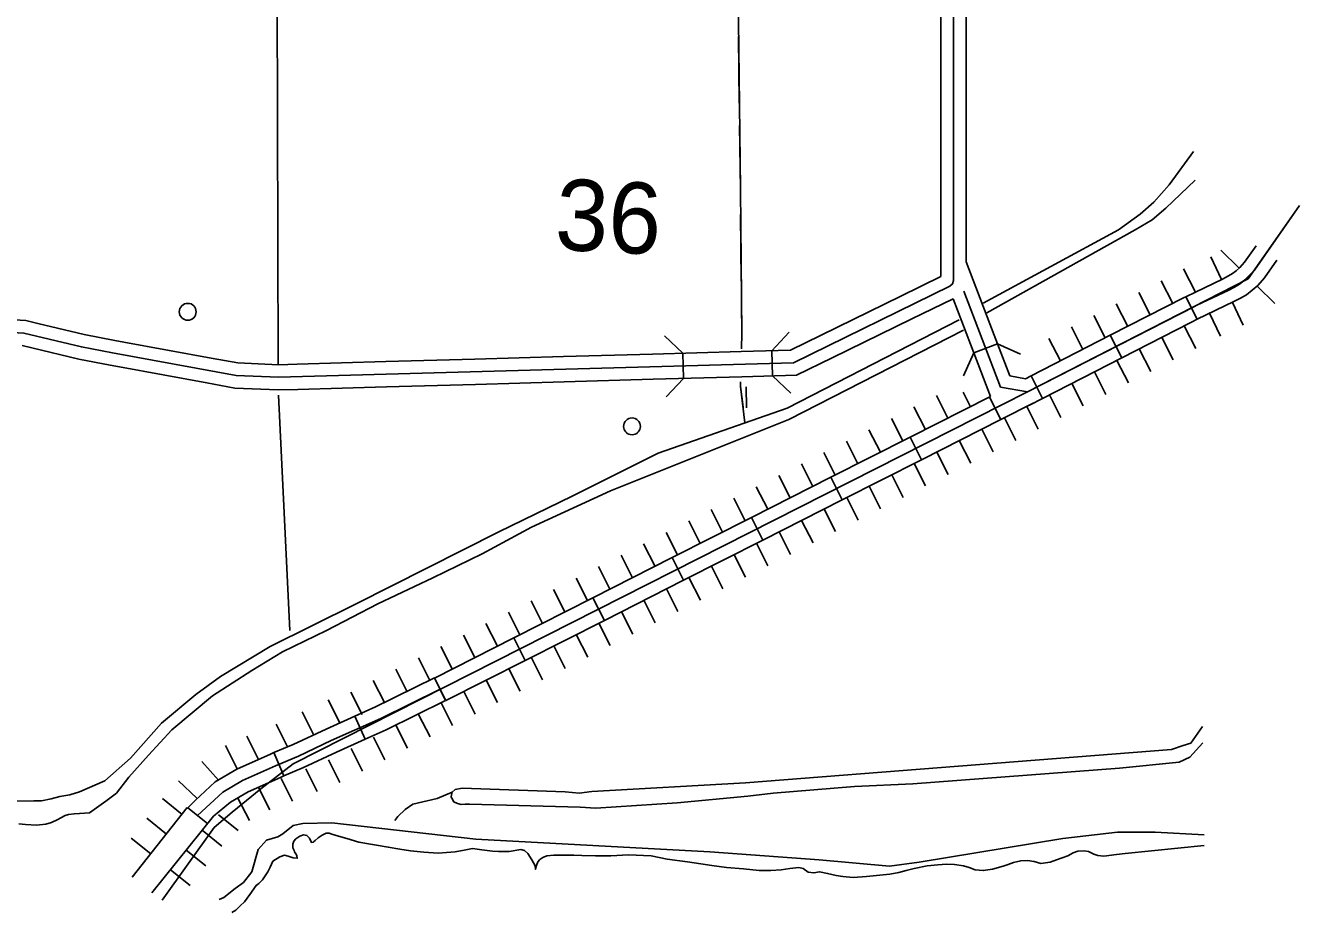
# Model space of a CAD drawing. Extents: x -4306 to 3843, y 131 to 8341.
# Drawn here: x 1170 to 2381, y 131 to 974 of the extents above; entities that cross this region are included whole.
import ezdxf

# ---------------------------------------------------------------- set-up
doc = ezdxf.new("R2010")
doc.units = 0
for name, color, linetype in [('32', 7, 'Continuous'), ('38', 7, 'Continuous'), ('52', 7, 'Continuous'), ('55', 7, 'Continuous'), ('56', 7, 'Continuous'), ('57', 7, 'Continuous'), ('63', 7, 'Continuous')]:
    doc.layers.add(name, color=color, linetype=linetype)

msp = doc.modelspace()

# ---------------------------------------------------------------- linework, layer by layer
at = {"layer": '32'}
for p, q in [((2040.2, 1016.8), (2040.1, 932.4)), ((2064.2, 1016.8), (2064.1, 932.4)), ((2040.1, 932.4), (2040.1, 847.9)), ((2064.1, 932.4), (2064.1, 847.9)), ((2040.1, 847.9), (2040.1, 763.4)), ((2064.1, 847.9), (2064.1, 763.4)), ((2338.4, 741.4), (2381.1, 802.6)), ((2040.1, 763.4), (2040.1, 735.2)), ((2064.1, 763.4), (2064.1, 748.9)), ((2328.9, 748.8), (2339.8, 764.4)), ((2090.7, 679.7), (2064.1, 749.2)), ((2317.4, 738), (2321, 740.8)), ((2321, 740.8), (2324.5, 743.8)), ((2324.5, 743.8), (2328.9, 748.8)), ((2333, 735.3), (2338.4, 741.4)), ((2347.8, 734), (2359.5, 750.7)), ((2040.1, 735.2), (2002.2, 716.7)), ((2282.1, 720.5), (2307.9, 732.8)), ((2307.9, 732.8), (2313.5, 735.9)), ((2313.5, 735.9), (2317.4, 738)), ((2319.3, 725.3), (2324, 728)), ((2324, 728), (2328.6, 731.5)), ((2328.6, 731.5), (2333, 735.3)), ((2341.5, 726.7), (2347.8, 734)), ((2002.2, 716.7), (1926.3, 679.6)), ((2096.8, 630.3), (2061.9, 721.4)), ((2271.5, 715.3), (2201.2, 679.4)), ((2273, 716), (2271.5, 715.3)), ((2282.1, 720.5), (2273, 716)), ((2273, 716), (2283.8, 694.8)), ((2283.6, 708), (2313.4, 722.1)), ((2313.4, 722.1), (2319.3, 725.3)), ((2318.8, 711.4), (2325.1, 714.8)), ((2325.1, 714.8), (2330.6, 717.9)), ((2330.6, 717.9), (2336.2, 722.2)), ((2336.2, 722.2), (2341.5, 726.7)), ((2051.8, 714.2), (2012.7, 695.1)), ((2068.3, 671.1), (2051.8, 714.2)), ((2281.9, 707.1), (2122.4, 625.6)), ((2283.8, 694.8), (2318.8, 711.4)), ((1170.2, 693.5), (1136.7, 695.4)), ((1181.5, 690.7), (1170.2, 693.5)), ((1225.5, 680.1), (1181.5, 690.7)), ((2012.7, 695.1), (1936.8, 658)), ((2277.3, 691.3), (2212.1, 658)), ((2279.1, 692.3), (2277.3, 691.3)), ((2283.8, 694.8), (2279.1, 692.3)), ((1254.9, 674.6), (1225.5, 680.1)), ((1926.3, 679.6), (1897.1, 665.3)), ((2093.9, 671.4), (2090.7, 679.7)), ((2201.2, 679.4), (2126, 640.9)), ((2201.2, 679.4), (2212.1, 658)), ((1175.9, 667.4), (1166.7, 669.6)), ((1220.5, 656.7), (1175.9, 667.4)), ((1263.4, 673), (1254.9, 674.6)), ((1346.5, 657.8), (1263.4, 673)), ((2071.5, 662.8), (2068.3, 671.1)), ((2093.9, 671.4), (2071.5, 662.8)), ((2105.6, 640.9), (2093.9, 671.4)), ((1250.5, 651), (1220.5, 656.7)), ((1371.7, 653.2), (1346.5, 657.8)), ((1512.5, 654.4), (1428.1, 652)), ((1597, 656.8), (1512.5, 654.4)), ((1681.4, 659.2), (1597, 656.8)), ((1765.9, 661.6), (1681.4, 659.2)), ((1850.3, 664), (1765.9, 661.6)), ((1795.6, 638.4), (1794.9, 662.4)), ((1897.1, 665.3), (1850.3, 664)), ((1880, 640.8), (1879.4, 664.8)), ((1936.8, 658), (1903, 641.5)), ((2087.4, 621.3), (2071.5, 662.8)), ((2212.1, 658), (2136.9, 619.5)), ((1259.1, 649.4), (1250.5, 651)), ((1342.2, 634.2), (1259.1, 649.4)), ((1410.4, 651.5), (1371.7, 653.2)), ((1428.1, 652), (1410.4, 651.5)), ((1369, 629.3), (1342.2, 634.2)), ((1513.2, 630.4), (1428.7, 628)), ((1597.6, 632.8), (1513.2, 630.4)), ((1682.1, 635.2), (1597.6, 632.8)), ((1766.6, 637.6), (1682.1, 635.2)), ((1851, 640), (1766.6, 637.6)), ((1903, 641.5), (1851, 640)), ((2122.4, 625.6), (2096.8, 630.3)), ((2120.6, 638.1), (2105.6, 640.9)), ((2126, 640.9), (2120.6, 638.1)), ((2126, 640.9), (2136.9, 619.5)), ((1410.2, 627.5), (1369, 629.3)), ((1428.7, 628), (1410.2, 627.5)), ((1424.2, 272.3), (2122.4, 625.6)), ((2010.9, 582.6), (2087.4, 621.3)), ((2097.2, 599.4), (2086.3, 620.8)), ((2136.9, 619.5), (2124.3, 613.1)), ((2097.2, 599.4), (2127.9, 614.9)), ((2021.8, 561.2), (2097.2, 599.4)), ((1935.5, 544.5), (2010.9, 582.6)), ((2021.8, 561.2), (2010.9, 582.6)), ((1946.4, 523.1), (2021.8, 561.2)), ((1860.2, 506.3), (1935.5, 544.5)), ((1946.4, 523.1), (1935.5, 544.5)), ((1871, 484.9), (1946.4, 523.1)), ((1784.8, 468.2), (1860.2, 506.3)), ((1871, 484.9), (1860.2, 506.3)), ((1795.6, 446.8), (1871, 484.9)), ((1709.4, 430.1), (1784.8, 468.2)), ((1795.6, 446.8), (1784.8, 468.2)), ((1720.2, 408.6), (1795.6, 446.8)), ((1634, 391.9), (1709.4, 430.1)), ((1720.2, 408.6), (1709.4, 430.1)), ((1644.8, 370.5), (1720.2, 408.6)), ((1558.6, 353.8), (1634, 391.9)), ((1644.8, 370.5), (1634, 391.9)), ((1569.4, 332.4), (1644.8, 370.5)), ((1558.7, 353.9), (1502.5, 326.4)), ((1569.4, 332.4), (1558.6, 353.8)), ((1558.7, 353.9), (1569.3, 332.3)), ((1564, 343.1), (1507.6, 315.5)), ((1569.3, 332.3), (1512.7, 304.6)), ((1482.9, 317.6), (1455.6, 305.3)), ((1507.6, 315.5), (1460.6, 294.4)), ((1502.5, 326.4), (1482.9, 317.6)), ((1482.9, 317.6), (1492.7, 295.7)), ((1455.6, 305.3), (1424.4, 290.6)), ((1512.7, 304.6), (1492.7, 295.7)), ((1460.6, 294.4), (1429.3, 279.7)), ((1492.7, 295.7), (1465.6, 283.5)), ((1402.7, 281.4), (1370.8, 267.2)), ((1406.1, 282.9), (1402.7, 281.4)), ((1424.4, 290.6), (1406.1, 282.9)), ((1406.1, 282.9), (1415.5, 260.8)), ((1429.3, 279.7), (1407.5, 270.4)), ((1465.6, 283.5), (1434.2, 268.7)), ((1370.8, 267.2), (1350.3, 255.2)), ((1407.5, 270.4), (1376.2, 256.5)), ((1393.6, 248.5), (1424.2, 272.3)), ((1434.2, 268.7), (1415.5, 260.8)), ((1350.3, 255.2), (1331.1, 237.3)), ((1376.2, 256.5), (1357.5, 245.5)), ((1412.2, 259.4), (1381.7, 245.8)), ((1415.5, 260.8), (1412.2, 259.4)), ((1357.5, 245.5), (1333.5, 223.1)), ((1381.7, 245.8), (1364.7, 235.8)), ((1366.5, 226.5), (1393.6, 248.5)), ((1323.7, 230.9), (1271.2, 164.7)), ((1331.1, 237.3), (1324.1, 230.6)), ((1324.1, 230.6), (1342.8, 215.6)), ((1364.7, 235.8), (1348.5, 222.7)), ((1348.5, 222.7), (1289.9, 149.7)), ((1349.3, 211.7), (1366.5, 226.5)), ((1299.7, 142.8), (1349.3, 211.7))]:
    msp.add_line(p, q, dxfattribs=at)
msp.add_lwpolyline([(2052.2, 1131.5), (2052.1, 731.6), (2051.2, 728.2), (2048.7, 726.1), (1900.1, 653.4), (1410.3, 639.5), (1370.3, 641.2), (1252.7, 662.8), (1223, 668.4), (1168.4, 681.6), (1136.3, 683.4), (569.9, 686.2), (-271.6, 689.6)], dxfattribs=at)
at = {"layer": '38'}
for p, q in [((2115.9, 661.6), (2093.9, 671.4)), ((2071.5, 662.8), (2061.8, 640.9))]:
    msp.add_line(p, q, dxfattribs=at)
for points in [[(1777.5, 678.9), (1794.9, 662.4)], [(1879.4, 664.8), (1895.9, 682.3)], [(1795.6, 638.4), (1779.1, 621)], [(1897.5, 624.4), (1880.1, 640.8)]]:
    msp.add_lwpolyline(points, dxfattribs=at)
at = {"layer": '52'}
for p, q in [((1410, 651.5), (1409, 1032.3)), ((1421.2, 398.9), (1410.3, 622.4))]:
    msp.add_line(p, q, dxfattribs=at)
at = {"layer": '55'}
msp.add_line((1855.1, 630.6), (1855.4, 610.5), dxfattribs=at)
at = {"layer": '56'}
for points in [[(1844.6, 1438.5), (1845.3, 1319.7), (1845.8, 1216.3), (1847.4, 1094.1), (1847.3, 1005.2), (1849.5, 818.3), (1850.8, 681.6), (1850.5, 666.5)], [(1847.8, 963.2), (1848.1, 931.5)], [(1848.1, 931.5), (1848.5, 899.9)], [(1848.8, 878.7), (1849.5, 818.3), (1849.6, 815.4)], [(2080.4, 710), (2209.1, 779.6), (2229.5, 794.6), (2242.6, 805.9), (2257.1, 822.3), (2280.2, 854)], [(2282, 826.8), (2254.1, 800.3), (2241.2, 789), (2224.9, 779.7), (2083.9, 700.8)], [(1849.7, 794.3), (1850.3, 730.9)], [(1850.5, 709.8), (1850.8, 681.6), (1850.5, 666.5)], [(1221.1, 245.6), (1245.2, 256.2), (1269.8, 277.5), (1299.1, 310.8), (1331.7, 338.2), (1355.4, 355.1), (1402.5, 383.6), (1483.7, 424), (1619.8, 492.6), (1689.7, 526.6), (1771.4, 567.3), (1893.9, 610.3), (2057.6, 694.2)], [(2061.7, 684.4), (1895.6, 599.5), (1726, 531.8), (1650.8, 497.2), (1603.9, 471.8), (1557, 449.1), (1504.8, 424.3), (1456.1, 399), (1414.2, 378.6), (1385.2, 361.1), (1347.5, 337), (1309, 304.6), (1286.7, 280.6), (1268.1, 259.5), (1256.3, 244.5), (1246.3, 236.9), (1230.7, 225.6)], [(1849.8, 635.2), (1849.7, 630.8), (1852.1, 611)], [(1849.8, 635.2), (1849.7, 630.8), (1853.9, 596.2)], [(2289, 307.7), (2277.7, 291.8), (2270.6, 289.7), (2259.3, 285.8), (1854.4, 254.3)], [(1585.1, 249.1), (1578.4, 247.8), (1575.5, 245.3), (1574.8, 242.7), (1574.5, 240.5), (1575.1, 239.5), (1577, 236.3), (1580.5, 234.6), (1584, 233.7), (1587.9, 234), (1592, 233.9), (1697.2, 231), (1712, 230.2), (1789.4, 235.1), (1856.6, 241.4), (1880.6, 244.5), (1958.1, 250.7), (2013.4, 253.2), (2209.9, 268.2), (2266.8, 274), (2276.9, 278.7), (2289.2, 292.3)], [(1221.1, 245.6), (1212, 242.8), (1202.6, 241.1), (1194.3, 238.9), (1185.2, 237.2), (1177.8, 237), (1159, 236.9), (1138, 237), (1124.7, 238), (1104.9, 239.4), (1084.9, 241.1), (1071.8, 242.2), (1057.2, 243.6), (1045.7, 244), (1035, 244.8), (1022.2, 245.9), (1015.7, 245.7), (1006.9, 245.6), (1002.7, 246.8), (1002.7, 246.9)], [(1575.5, 245.3), (1561.4, 239.3), (1538, 234), (1530.9, 228.9), (1523.8, 222.2), (1521.1, 218.3)], [(1854.4, 254.3), (1708.2, 246), (1696.4, 244.4), (1682.9, 245.8), (1585.1, 249.1)], [(1230.7, 225.6), (1221.2, 225.2), (1216.1, 224.7), (1210.6, 224.2), (1207.6, 223.1), (1203.6, 221), (1200.6, 219.4), (1194.5, 216.5), (1189.1, 215), (1180.4, 213.9), (1169.9, 214.7), (1163.5, 215.3)], [(1354.1, 143.4), (1358.3, 145.4), (1369.3, 153.7), (1377.1, 159.5), (1385.1, 169.8), (1391.2, 190.8), (1399.1, 199.8), (1409.9, 203), (1414.4, 205.9), (1424.2, 213.6), (1433.6, 215.6), (1461.2, 216.2), (1598, 200.7), (1820.6, 188.6), (1924.6, 181), (1991.2, 175.2), (2019.5, 178.8), (2156, 201.2)], [(2290.5, 194.7), (2215.3, 187), (2207.2, 186.2), (2195.2, 184.4), (2189.4, 185.2), (2185.6, 186.5), (2180.6, 188.9), (2176.3, 189.6), (2170.4, 189.2), (2165.9, 187.7), (2161, 185), (2155.5, 182.9), (2150.1, 181.1), (2144, 178.7), (2135.1, 177.7), (2128.8, 179.4), (2122.4, 180.5), (2116.1, 180.2), (2109.3, 178.4), (2104.1, 176.6), (2099.3, 174.9), (2089.2, 172.3), (2080.4, 170.8), (2072.7, 171.6), (2067.1, 173.7), (2061.7, 175.4), (2053.1, 176.5), (2045.6, 176.8), (2037.2, 176.3), (2027.2, 175.5), (2014.7, 172.7), (2007.2, 170.8), (2000.2, 168.9), (1991.5, 167.4), (1978.9, 166.1), (1969.5, 165.1), (1956.9, 164.4), (1947.1, 165.2), (1940.7, 166.2), (1932.4, 168.1), (1924.7, 169.8), (1919.4, 168.7), (1914.1, 169.3), (1909.3, 172.8), (1905, 173.8), (1896.7, 172.9), (1888.4, 171.6), (1878.5, 171), (1867.3, 170.9), (1852.4, 172.4), (1836.4, 173.9), (1822.5, 175.7), (1812, 177.4), (1799.2, 179.1), (1780, 181.6), (1764.6, 184.8), (1743.2, 185.7), (1726.4, 184.9), (1711.8, 184.9), (1698.7, 185.3), (1691.1, 185.6), (1672.2, 185.6), (1665.5, 184.9), (1661.8, 183.3), (1658.9, 181.5), (1657, 179.1), (1655.6, 175.6), (1654.6, 172), (1654.3, 175.3), (1651.4, 181.2), (1647.4, 187.1), (1644.4, 190), (1640.7, 190.9), (1629.6, 189.1), (1619.7, 189.1), (1614, 189.3), (1603.7, 190.5), (1594.8, 191.8), (1587, 190.3), (1578.5, 188.7), (1570.2, 187.9), (1562.2, 187.5), (1548.7, 188.3), (1536, 189.6), (1525.7, 191.3), (1514.8, 193.2), (1486.7, 197.9), (1475.3, 201.4), (1467.5, 203.7), (1461.1, 205.6), (1458.5, 206.4), (1455.8, 206.5), (1451.8, 204.6), (1448, 202), (1445.3, 199.5), (1443.8, 198.3)], [(2290.4, 204.9), (2244, 207.3), (2208.1, 207.3), (2156, 201.2)], [(1443.8, 197.9), (1441.7, 197.6), (1439.8, 201.8), (1437.4, 204.3), (1434.2, 204.8), (1430.8, 203.7), (1427, 201.1), (1425.1, 198.8), (1424, 196.1), (1424.1, 192.4), (1425.3, 190), (1425.7, 188.7), (1427.5, 185.7), (1427.8, 184.9), (1428.3, 182.5), (1424.5, 183.1), (1419.5, 184.5), (1416, 185.5), (1411.7, 183.9), (1405.1, 179.7), (1402.4, 174.2), (1400.1, 169.7), (1397.2, 164.9), (1395.1, 162), (1391.8, 158.7), (1389.1, 156.7), (1383.2, 148.2), (1378.1, 141.1), (1373.9, 137.3), (1369.8, 133.1), (1366.1, 131)]]:
    msp.add_lwpolyline(points, dxfattribs=at)
at = {"layer": '57'}
for centre in [(1324.1, 701.8), (1746.5, 592.9)]:
    msp.add_circle(centre, 8, dxfattribs=at)
at = {"layer": '63'}
for p, q in [((2381.1, 802.6), (2332.4, 733)), ((2381.1, 802.6), (2332.4, 733)), ((2381.1, 802.6), (2338.4, 741.4)), ((2365.1, 779.6), (2332.4, 733)), ((2296.7, 754.1), (2307, 732.4)), ((2306.3, 760.2), (2323.7, 743.1)), ((2270.8, 742.5), (2282.1, 720.5)), ((2338.4, 741.4), (2328.6, 731.5)), ((2332.4, 733), (2122.4, 625.6)), ((2332.4, 733), (2122.4, 625.6)), ((2332.4, 733), (2122.4, 625.6)), ((2249.7, 731.1), (2260.6, 709.7)), ((2328.6, 731.5), (2313.4, 722.1)), ((2228.3, 720.2), (2239.2, 698.8)), ((2228.3, 720.2), (2239.2, 698.8)), ((2313.4, 722.1), (2283.6, 708)), ((2340.8, 726.2), (2357.6, 709.7)), ((2206.9, 709.3), (2217.9, 687.9)), ((2317.3, 710.7), (2327.6, 689)), ((2185.6, 698.3), (2196.5, 677)), ((2295.7, 700.4), (2306, 678.7)), ((2295.7, 700.4), (2306, 678.7)), ((2164.2, 687.4), (2175.1, 666)), ((2164.2, 687.4), (2175.1, 666)), ((2271.5, 688.4), (2282.5, 667)), ((2142.8, 676.5), (2153.8, 655.1)), ((2228.8, 666.5), (2239.7, 645.1)), ((2250.2, 677.4), (2261.1, 656.1)), ((2250.2, 677.4), (2261.1, 656.1)), ((2207.4, 655.6), (2218.4, 634.2)), ((2186.1, 644.7), (2197, 623.3)), ((2186.1, 644.7), (2197, 623.3)), ((2164.7, 633.7), (2175.6, 612.4)), ((2122.4, 625.6), (1424.2, 272.3)), ((2122.4, 625.6), (1424.2, 272.3)), ((2122.4, 625.6), (1424.2, 272.3)), ((2036, 622.2), (2046.8, 600.8)), ((2036, 622.2), (2046.8, 600.8)), ((2061.2, 625.5), (2068.2, 611.6)), ((2143.3, 622.8), (2154.3, 601.4)), ((2014.6, 611.4), (2025.4, 589.9)), ((2121.9, 611.9), (2132.7, 590.4)), ((2121.9, 611.9), (2132.7, 590.4)), ((1993.1, 600.5), (2004, 579.1)), ((2100.5, 601), (2111.3, 579.6)), ((1971.7, 589.7), (1982.6, 568.3)), ((1971.7, 589.7), (1982.6, 568.3)), ((2079.1, 590.2), (2089.9, 568.8)), ((1950.3, 578.9), (1961.1, 557.4)), ((2057.6, 579.4), (2068.5, 557.9)), ((2057.6, 579.4), (2068.5, 557.9)), ((1928.9, 568), (1939.7, 546.6)), ((2014.8, 557.7), (2025.6, 536.3)), ((2036.2, 568.5), (2047.1, 547.1)), ((1886, 546.3), (1896.9, 524.9)), ((1907.5, 557.2), (1918.3, 535.8)), ((1907.5, 557.2), (1918.3, 535.8)), ((1993.4, 546.9), (2004.2, 525.4)), ((1993.4, 546.9), (2004.2, 525.4)), ((1864.6, 535.5), (1875.5, 514.1)), ((1972, 536), (1982.8, 514.6)), ((1843.2, 524.7), (1854, 503.3)), ((1843.2, 524.7), (1854, 503.3)), ((1950.6, 525.2), (1961.4, 503.8)), ((1821.8, 513.8), (1832.6, 492.4)), ((1929.1, 514.3), (1940, 492.9)), ((1929.1, 514.3), (1940, 492.9)), ((1800.4, 503), (1811.2, 481.6)), ((1907.7, 503.5), (1918.6, 482.1)), ((1779, 492.2), (1789.8, 470.7)), ((1779, 492.2), (1789.8, 470.7)), ((1886.3, 492.7), (1897.1, 471.3)), ((1757.5, 481.3), (1768.4, 459.9)), ((1864.9, 481.8), (1875.7, 460.4)), ((1864.9, 481.8), (1875.7, 460.4)), ((1736.1, 470.5), (1747, 449.1)), ((1843.5, 471), (1854.3, 449.6)), ((1693.3, 448.8), (1704.1, 427.4)), ((1714.7, 459.7), (1725.5, 438.2)), ((1714.7, 459.7), (1725.5, 438.2)), ((1800.6, 449.3), (1811.5, 427.9)), ((1800.6, 449.3), (1811.5, 427.9)), ((1822, 460.2), (1832.9, 438.7)), ((1671.9, 438), (1682.7, 416.6)), ((1779.2, 438.5), (1790.1, 417.1)), ((1650.5, 427.2), (1661.3, 405.7)), ((1650.5, 427.2), (1661.3, 405.7)), ((1757.8, 427.7), (1768.6, 406.2)), ((1629, 416.3), (1639.9, 394.9)), ((1736.4, 416.8), (1747.2, 395.4)), ((1736.4, 416.8), (1747.2, 395.4)), ((1607.6, 405.5), (1618.5, 384.1)), ((1715, 406), (1725.8, 384.6)), ((1586.2, 394.6), (1597, 373.2)), ((1586.2, 394.6), (1597, 373.2)), ((1693.5, 395.2), (1704.4, 373.7)), ((1564.8, 383.8), (1575.6, 362.4)), ((1672.1, 384.3), (1683, 362.9)), ((1672.1, 384.3), (1683, 362.9)), ((1543.4, 373), (1554.2, 351.6)), ((1650.7, 373.5), (1661.5, 352.1)), ((1500.5, 351.3), (1511.4, 329.9)), ((1522, 362.1), (1532.8, 340.7)), ((1522, 362.1), (1532.8, 340.7)), ((1607.9, 351.8), (1618.7, 330.4)), ((1607.9, 351.8), (1618.7, 330.4)), ((1629.3, 362.6), (1640.1, 341.2)), ((1479.1, 340.5), (1490, 319)), ((1586.5, 341), (1597.3, 319.6)), ((1457.5, 333.2), (1468.3, 311.8)), ((1565, 330.1), (1575.9, 308.7)), ((1432.9, 321.7), (1443.7, 300.3)), ((1543.6, 319.3), (1554.5, 297.9)), ((1543.6, 319.3), (1554.5, 297.9)), ((1408.2, 309.9), (1419.1, 288.5)), ((1522.2, 308.5), (1533, 287)), ((1380.3, 298.5), (1391.1, 277.1)), ((1500.8, 297.6), (1511.6, 276.2)), ((1360, 289.6), (1370.9, 268.2)), ((1479.4, 286.8), (1490.2, 265.4)), ((1479.4, 286.8), (1490.2, 265.4)), ((1337.6, 274.6), (1353.4, 256.6)), ((1424.2, 272.3), (1393.6, 248.5)), ((1424.2, 272.3), (1393.6, 248.5)), ((1424.2, 272.3), (1393.6, 248.5)), ((1436.3, 267.5), (1447.1, 246.1)), ((1458, 276), (1468.8, 254.5)), ((1315.2, 256), (1332.8, 239.7)), ((1412.8, 258.4), (1423.6, 236.9)), ((1393.6, 248.5), (1366.5, 226.5)), ((1393.6, 248.5), (1366.5, 226.5)), ((1393.6, 248.5), (1366.5, 226.5)), ((1391.4, 249.9), (1402.2, 228.5)), ((1300.2, 239.2), (1318.9, 224.2)), ((1371.8, 239.7), (1382.7, 218.3)), ((1285.2, 220.5), (1303.9, 205.4)), ((1366.5, 226.5), (1349.3, 211.7)), ((1366.5, 226.5), (1349.3, 211.7)), ((1366.5, 226.5), (1349.3, 211.7)), ((1353.4, 223.8), (1372.2, 208.8)), ((1349.3, 211.7), (1299.7, 142.8)), ((1349.3, 211.7), (1299.7, 142.8)), ((1349.3, 211.7), (1299.7, 142.8)), ((1337.7, 209.1), (1356.4, 194.1)), ((1270.2, 201.7), (1288.9, 186.7)), ((1270.2, 201.7), (1288.9, 186.7)), ((1322.6, 190.4), (1341.4, 175.4)), ((1307.6, 171.7), (1326.3, 156.7)), ((1307.6, 171.7), (1326.3, 156.7))]:
    msp.add_line(p, q, dxfattribs=at)

# ---------------------------------------------------------------- texts
at = {"layer": '52'}
msp.add_text('36', height=67.59, rotation=357.2006, dxfattribs=at).set_placement((1672.4, 760.9))

doc.saveas('drawing.dxf')
